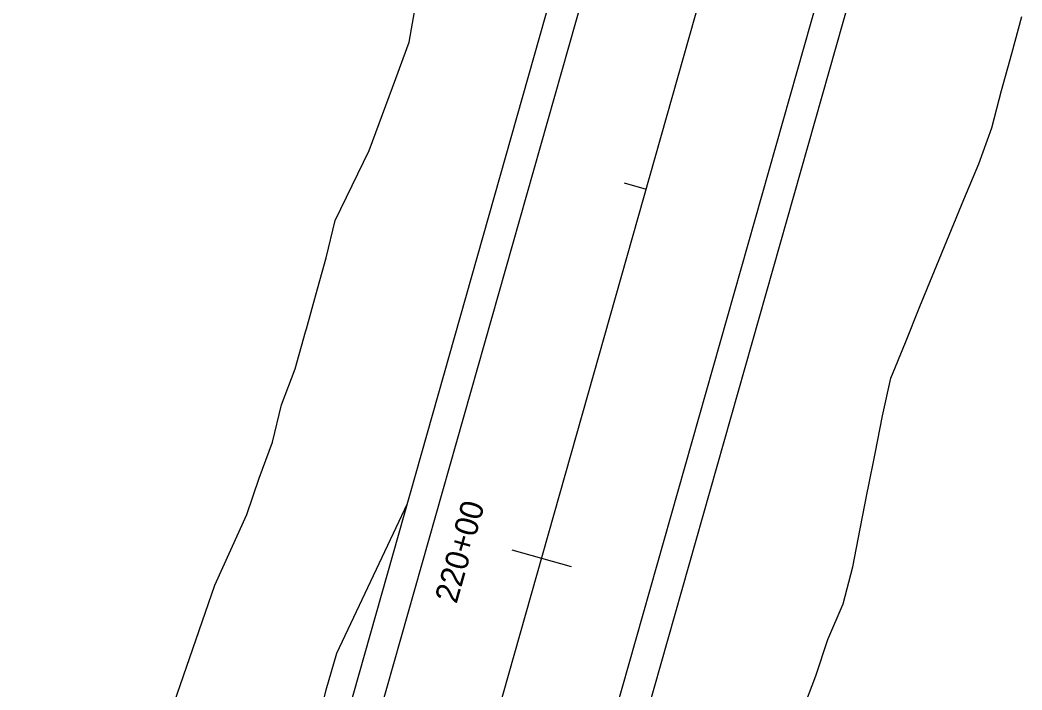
# Model space of a CAD drawing. Extents: x 1441466 to 1476381, y 2042742 to 2057194.
# Drawn here: x 1445810.7 to 1446071.8, y 2054905.9 to 2055080.6 of the extents above; entities that cross this region are included whole.
import ezdxf

# ---------------------------------------------------------------- set-up
doc = ezdxf.new("R2010")
doc.units = 0
for name, color, linetype in [('R_Horz Alg', 7, 'Continuous'), ('R_Horz Alg Stationing', 7, 'Continuous'), ('R_Proposed Const Limits', 7, 'Continuous'), ('R_Proposed Road', 7, 'Continuous'), ('R_Shld', 7, 'Continuous')]:
    doc.layers.add(name, color=color, linetype=linetype)

msp = doc.modelspace()

# ---------------------------------------------------------------- linework, layer by layer
at = {"layer": 'R_Horz Alg'}
msp.add_line((1445886.03, 2054726.64), (1446009.58, 2055162.32), dxfattribs=at)
at = {"layer": 'R_Horz Alg Stationing'}
for points in [[(1445968.13, 2055038.13), (1445973.9, 2055036.49)], [(1445938.92, 2054942.47), (1445954.31, 2054938.1)]]:
    msp.add_lwpolyline(points, dxfattribs=at)
at = {"layer": 'R_Proposed Const Limits'}
for points in [[(1445861.45, 2054933.26), (1445865.63, 2054942.46), (1445869.79, 2054951.68), (1445873.02, 2054961.16), (1445876.49, 2054970.57), (1445878.88, 2054980.28), (1445882.39, 2054989.69), (1445885.11, 2054999.31), (1445885.33, 2055000.11), (1445887.81, 2055008.94), (1445890.48, 2055018.57), (1445892.85, 2055028.29), (1445897.24, 2055037.44), (1445901.7, 2055046.57), (1445905.18, 2055055.98), (1445908.69, 2055065.38), (1445912.17, 2055074.79), (1445913.89, 2055084.69)], [(1446014.58, 2054900.22), (1446018.15, 2054909.6), (1446021.28, 2054919.11), (1446025.24, 2054928.38), (1446027.75, 2054938.06), (1446029.67, 2054947.91), (1446031.61, 2054957.76), (1446031.77, 2054958.58), (1446033.56, 2054967.6), (1446035.51, 2054977.44), (1446037.71, 2054987.21), (1446041.48, 2054996.54), (1446045.26, 2055005.86), (1446049.06, 2055015.18), (1446052.88, 2055024.49), (1446056.73, 2055033.79), (1446060.6, 2055043.09), (1446063.99, 2055052.52), (1446066.54, 2055062.19), (1446069.18, 2055071.84), (1446071.85, 2055081.48)], [(1445810.71, 2054739.64), (1445824.94, 2054787.7), (1445826.36, 2054794.22), (1445826, 2054797.79), (1445825.05, 2054808.45), (1445824.84, 2054818.91), (1445824.13, 2054829.5), (1445826.32, 2054839.28), (1445829.03, 2054845.44), (1445830.06, 2054848.61), (1445834.1, 2054857.86), (1445837.94, 2054865.83), (1445837.94, 2054865.83), (1445838.51, 2054867), (1445841.87, 2054876.44), (1445861.45, 2054933.26)]]:
    msp.add_lwpolyline(points, dxfattribs=at)
at = {"layer": 'R_Proposed Road'}
for p, q in [((1445850.48, 2054738.8), (1445974.04, 2055174.48)), ((1445857.64, 2054734.69), (1445981.2, 2055170.37)), ((1445914.41, 2054718.59), (1446037.96, 2055154.27)), ((1445922.1, 2054716.41), (1446045.66, 2055152.09))]:
    msp.add_line(p, q, dxfattribs=at)
at = {"layer": 'R_Shld'}
for p, q in [((1445893.26, 2054915.56), (1445911.66, 2054954.54)), ((1445890.53, 2054905.94), (1445893.26, 2054915.56)), ((1445846.21, 2054736.6), (1445890.53, 2054905.94))]:
    msp.add_line(p, q, dxfattribs=at)

# ---------------------------------------------------------------- texts
at = {"layer": 'R_Horz Alg Stationing'}
msp.add_text('220+00', height=6, rotation=74.1667, dxfattribs=at).set_placement((1445924.48, 2054928.22))

doc.saveas('drawing.dxf')
